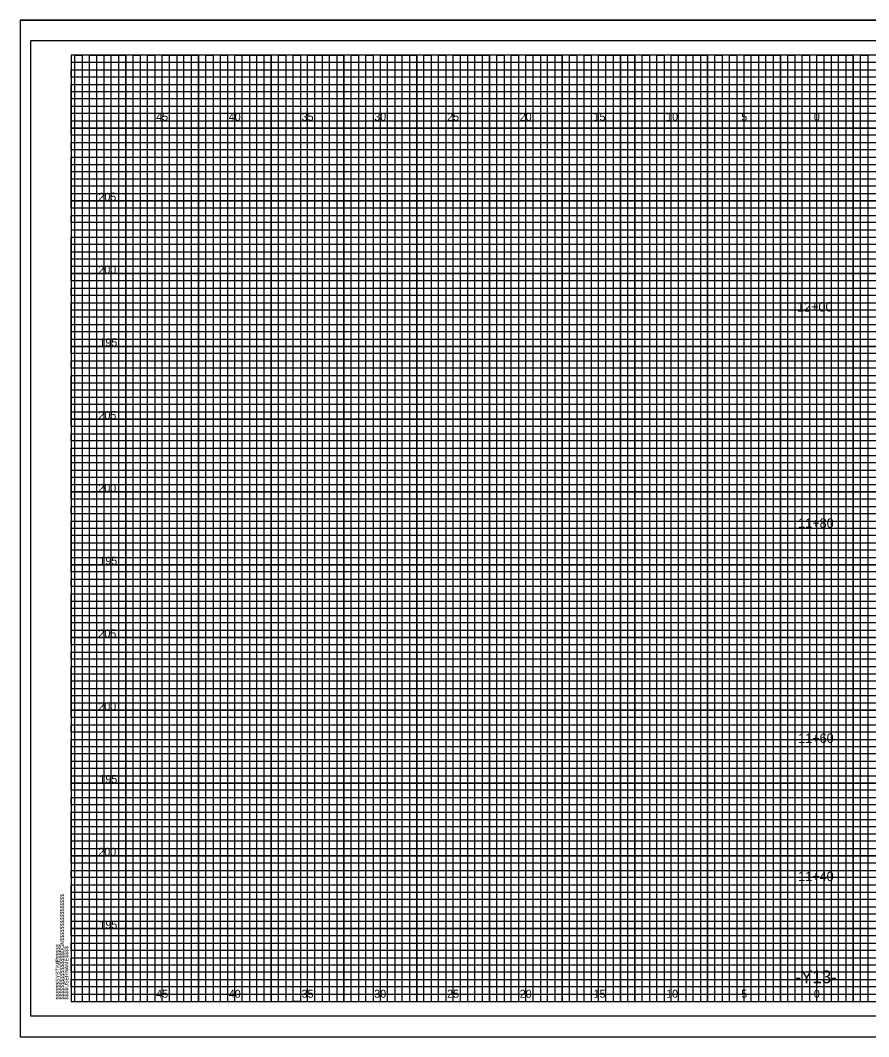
# Model space of a CAD drawing. Extents: x -4 to 103, y -2 to 209.
# Drawn here: x -3.5 to 54.8, y -2.4 to 67.4 of the extents above; entities that cross this region are included whole.
import ezdxf

# ---------------------------------------------------------------- set-up
doc = ezdxf.new("R2010")
doc.units = 0
for name, color, linetype in [('Exist XS Ground Line', 7, 'Continuous'), ('Old_Level_10', 7, 'Continuous'), ('Old_Level_16', 7, 'Continuous'), ('Old_Level_3', 7, 'Continuous'), ('Old_Level_5', 7, 'Continuous'), ('Old_Level_8', 7, 'Continuous'), ('Prop XS Finish Grade Earthwork', 7, 'Continuous'), ('Prop XS Finish Grade Pavement', 7, 'Continuous'), ('Prop XS Pvmt Edge Slope', 7, 'Continuous'), ('Prop XS SE Text', 7, 'Continuous'), ('Prop XS Suitable Common Exc Shape', 7, 'Continuous')]:
    doc.layers.add(name, color=color, linetype=linetype)

msp = doc.modelspace()

# ---------------------------------------------------------------- linework, layer by layer
at = {"layer": 'Exist XS Ground Line'}
msp.add_lwpolyline([(103, 66), (-2.8, 66), (-2.8, -1), (103, -1)], close=True, dxfattribs=at)
at = {"layer": 'Old_Level_10'}
for p, q in [((1.25, 0), (1.25, 65)), ((3.75, 0), (3.75, 65)), ((6.25, 0), (6.25, 65)), ((8.75, 0), (8.75, 65)), ((11.25, 0), (11.25, 65)), ((13.75, 0), (13.75, 65)), ((16.25, 0), (16.25, 65)), ((18.75, 0), (18.75, 65)), ((21.25, 0), (21.25, 65)), ((23.75, 0), (23.75, 65)), ((26.25, 0), (26.25, 65)), ((28.75, 0), (28.75, 65)), ((31.25, 0), (31.25, 65)), ((33.75, 0), (33.75, 65)), ((36.25, 0), (36.25, 65)), ((38.75, 0), (38.75, 65)), ((41.25, 0), (41.25, 65)), ((43.75, 0), (43.75, 65)), ((46.25, 0), (46.25, 65)), ((48.75, 0), (48.75, 65)), ((51.25, 0), (51.25, 65)), ((53.75, 0), (53.75, 65)), ((0, 62.5), (74.25, 62.5)), ((0, 60), (102.5, 60)), ((0, 57.5), (102.5, 57.5)), ((0, 55), (102.5, 55)), ((0, 52.5), (102.5, 52.5)), ((0, 50), (102.5, 50)), ((0, 47.5), (102.5, 47.5)), ((0, 45), (102.5, 45)), ((0, 42.5), (102.5, 42.5)), ((0, 40), (102.5, 40)), ((0, 37.5), (102.5, 37.5)), ((0, 35), (102.5, 35)), ((0, 32.5), (102.5, 32.5)), ((0, 30), (102.5, 30)), ((0, 27.5), (102.5, 27.5)), ((0, 25), (102.5, 25)), ((0, 22.5), (102.5, 22.5)), ((0, 20), (102.5, 20)), ((0, 17.5), (102.5, 17.5)), ((0, 15), (102.5, 15)), ((0, 12.5), (102.5, 12.5)), ((0, 10), (102.5, 10)), ((0, 7.5), (102.5, 7.5)), ((0, 5), (102.5, 5)), ((0, 2.5), (102.5, 2.5))]:
    msp.add_line(p, q, dxfattribs=at)
at = {"layer": 'Old_Level_3'}
for p, q in [((-3.5, 67.4), (103.4, 67.4)), ((-3.5, 67.4), (-3.5, -2.425)), ((-3.5, -2.425), (103.4, -2.425))]:
    msp.add_line(p, q, dxfattribs=at)
at = {"layer": 'Old_Level_5'}
msp.add_lwpolyline([(103.4, 67.4), (-3.5, 67.4), (-3.5, -2.425), (103.4, -2.425)], close=True, dxfattribs=at)
at = {"layer": 'Old_Level_8'}
for points in [[(1.25, 0), (1.25, 65), (3.75, 65), (3.75, 0), (6.25, 0), (6.25, 65), (8.75, 65), (8.75, 0), (11.25, 0), (11.25, 65), (13.75, 65), (13.75, 0), (16.25, 0), (16.25, 65), (18.75, 65), (18.75, 0), (21.25, 0), (21.25, 65), (23.75, 65), (23.75, 0), (26.25, 0), (26.25, 65), (28.75, 65), (28.75, 0), (31.25, 0), (31.25, 65), (33.75, 65), (33.75, 0), (36.25, 0), (36.25, 65), (38.75, 65), (38.75, 0), (41.25, 0), (41.25, 65), (43.75, 65), (43.75, 0), (46.25, 0), (46.25, 65), (48.75, 65), (48.75, 0), (51.25, 0), (51.25, 65), (53.75, 65), (53.75, 0)], [(102.5, 60), (0, 60), (0, 62.5), (74.25, 62.5)], [(102.5, 55), (0, 55), (0, 57.5), (102.5, 57.5)], [(102.5, 50), (0, 50), (0, 52.5), (102.5, 52.5)], [(102.5, 45), (0, 45), (0, 47.5), (102.5, 47.5)], [(102.5, 40), (0, 40), (0, 42.5), (102.5, 42.5)], [(102.5, 35), (0, 35), (0, 37.5), (102.5, 37.5)], [(102.5, 30), (0, 30), (0, 32.5), (102.5, 32.5)], [(102.5, 25), (0, 25), (0, 27.5), (102.5, 27.5)], [(102.5, 20), (0, 20), (0, 22.5), (102.5, 22.5)], [(102.5, 15), (0, 15), (0, 17.5), (102.5, 17.5)], [(102.5, 10), (0, 10), (0, 12.5), (102.5, 12.5)], [(102.5, 5), (0, 5), (0, 7.5), (102.5, 7.5)], [(0, 2.5), (102.5, 2.5)]]:
    msp.add_lwpolyline(points, dxfattribs=at)
at = {"layer": 'Prop XS Finish Grade Earthwork'}
for points in [[(0.25, 0), (0.25, 65), (0.75, 65), (0.75, 0), (1.75, 0), (1.75, 65), (2.25, 65), (2.25, 0), (2.75, 0), (2.75, 65), (3.25, 65), (3.25, 0), (4.25, 0), (4.25, 65), (4.75, 65), (4.75, 0), (5.25, 0), (5.25, 65), (5.75, 65), (5.75, 0), (6.75, 0), (6.75, 65), (7.25, 65), (7.25, 0), (7.75, 0), (7.75, 65), (8.25, 65), (8.25, 0), (9.25, 0), (9.25, 65), (9.75, 65), (9.75, 0), (10.25, 0), (10.25, 65), (10.75, 65), (10.75, 0), (11.75, 0), (11.75, 65), (12.25, 65), (12.25, 0), (12.75, 0), (12.75, 65), (13.25, 65), (13.25, 0), (14.25, 0), (14.25, 65), (14.75, 65), (14.75, 0), (15.75, 0), (15.25, 0), (15.25, 65), (15.75, 65), (15.75, 0), (16.75, 0), (16.75, 65), (17.25, 65), (17.25, 0), (17.75, 0), (17.75, 65), (18.25, 65), (18.25, 0), (19.25, 0), (19.25, 65), (19.75, 65), (19.75, 0), (20.25, 0), (20.25, 65), (20.75, 65), (20.75, 0), (21.75, 0), (21.75, 65), (22.25, 65), (22.25, 0), (22.75, 0), (22.75, 65), (23.25, 65), (23.25, 0), (24.25, 0), (24.25, 65), (24.75, 65), (24.75, 0), (25.25, 0), (25.25, 65), (25.75, 65), (25.75, 0), (26.75, 0), (26.75, 65), (27.25, 65), (27.25, 0), (27.75, 0), (27.75, 65), (28.25, 65), (28.25, 0), (29.25, 0), (29.25, 65), (29.75, 65), (29.75, 0), (30.25, 0), (30.25, 65), (30.75, 65), (30.75, 0)], [(30.75, 0), (31.75, 0), (31.75, 65), (32.25, 65), (32.25, 0), (32.75, 0), (32.75, 65), (33.25, 65), (33.25, 0), (34.25, 0), (34.25, 65), (34.75, 65), (34.75, 0), (35.25, 0), (35.25, 65), (35.75, 65), (35.75, 0), (36.75, 0), (36.75, 65), (37.25, 65), (37.25, 0), (37.75, 0), (37.75, 65), (37.75, 0)], [(38.25, 65), (38.25, 0), (39.25, 0), (39.25, 65), (39.75, 65), (39.75, 0), (40.25, 0), (40.25, 65), (40.75, 65), (40.75, 0), (41.75, 0), (41.75, 65), (42.25, 65), (42.25, 0), (42.75, 0), (42.75, 65), (43.25, 65), (43.25, 0), (43.75, 0), (44.25, 0), (44.25, 65), (44.75, 65), (44.75, 0), (45.25, 0), (45.25, 65), (45.75, 65), (45.75, 0), (46.75, 0), (46.75, 65), (47.25, 65), (47.25, 0), (47.75, 0), (47.75, 65), (48.25, 65), (48.25, 0), (49.25, 0), (49.25, 65), (49.75, 65), (49.75, 0), (50.25, 0), (50.25, 65), (50.75, 65), (50.75, 0), (51.75, 0), (51.75, 65), (52.25, 65), (52.25, 0), (52.75, 0), (52.75, 65), (53.25, 65), (53.25, 0), (54.25, 0), (54.25, 65), (54.75, 65), (54.75, 0), (55.25, 0)], [(0, 62), (0, 63), (74.25, 63), (74.25, 63.5), (0, 63.5), (0, 64), (74.25, 64), (74.25, 64.5), (0, 64.5)], [(102.5, 62), (0, 62)], [(102.5, 61), (0, 61), (0, 61.5), (102.5, 61.5)], [(102.5, 59.5), (0, 59.5), (0, 60.5), (102.5, 60.5)], [(102.5, 58.5), (0, 58.5), (0, 59), (102.5, 59)], [(102.5, 57), (0, 57), (0, 58), (102.5, 58)], [(102.5, 56), (0, 56), (0, 56.5), (102.5, 56.5)], [(102.5, 54.5), (0, 54.5), (0, 55.5), (102.5, 55.5)], [(102.5, 53.5), (0, 53.5), (0, 54), (102.5, 54)], [(0, 53), (102.5, 53)], [(102.5, 52), (0, 52)], [(102.5, 51), (0, 51), (0, 51.5), (102.5, 51.5)], [(102.5, 49.5), (0, 49.5), (0, 50.5), (102.5, 50.5)], [(102.5, 48.5), (0, 48.5), (0, 49), (102.5, 49)], [(102.5, 47), (0, 47), (0, 48), (102.5, 48)], [(102.5, 46), (0, 46), (0, 46.5), (102.5, 46.5)], [(102.5, 44.5), (0, 44.5), (0, 45.5), (102.5, 45.5)], [(102.5, 43.5), (0, 43.5), (0, 44), (102.5, 44)], [(102.5, 42), (0, 42), (0, 43), (102.5, 43)], [(102.5, 41), (0, 41), (0, 41.5), (102.5, 41.5)], [(102.5, 39.5), (0, 39.5), (0, 40.5), (102.5, 40.5)], [(102.5, 38.5), (0, 38.5), (0, 39), (102.5, 39)], [(102.5, 37), (0, 37), (0, 38), (102.5, 38)], [(102.5, 36), (0, 36), (0, 36.5), (102.5, 36.5)], [(102.5, 34.5), (0, 34.5), (0, 35.5), (102.5, 35.5)], [(102.5, 33.5), (0, 33.5), (0, 34), (102.5, 34)], [(102.5, 32), (0, 32), (0, 33), (102.5, 33)], [(102.5, 31), (0, 31), (0, 31.5)], [(0, 31.5), (102.5, 31.5)], [(102.5, 29.5), (0, 29.5), (0, 30.5), (102.5, 30.5)], [(102.5, 28.5), (0, 28.5), (0, 29), (102.5, 29)], [(102.5, 27), (0, 27), (0, 28), (102.5, 28)], [(102.5, 26), (0, 26), (0, 26.5), (102.5, 26.5)], [(102.5, 24.5), (0, 24.5), (0, 25.5), (102.5, 25.5)], [(102.5, 23.5), (0, 23.5), (0, 24), (102.5, 24)], [(102.5, 22), (0, 22), (0, 23), (102.5, 23)], [(102.5, 21), (0, 21), (0, 21.5), (102.5, 21.5)], [(102.5, 19.5), (0, 19.5), (0, 20.5), (102.5, 20.5)], [(102.5, 18.5), (0, 18.5), (0, 19), (102.5, 19)], [(102.5, 17), (0, 17), (0, 18), (102.5, 18)], [(102.5, 16), (0, 16), (0, 16.5), (102.5, 16.5)], [(102.5, 14.5), (0, 14.5), (0, 15.5), (102.5, 15.5)], [(102.5, 13.5), (0, 13.5), (0, 14), (102.5, 14)], [(102.5, 12), (0, 12), (0, 13), (102.5, 13)], [(102.5, 11), (0, 11), (0, 11.5), (102.5, 11.5)], [(102.5, 9.5), (0, 9.5), (0, 10.5), (102.5, 10.5)], [(102.5, 8.5), (0, 8.5), (0, 9), (102.5, 9)], [(102.5, 7), (0, 7), (0, 8), (102.5, 8)], [(102.5, 6), (0, 6), (0, 6.5), (102.5, 6.5)], [(102.5, 4.5), (0, 4.5), (0, 5.5), (102.5, 5.5)], [(102.5, 3.5), (0, 3.5), (0, 4), (102.5, 4)], [(102.5, 2), (0, 2), (0, 3), (102.5, 3)], [(102.5, 1), (0, 1), (0, 1.5), (102.5, 1.5)], [(0, 0.5), (102.5, 0.5)]]:
    msp.add_lwpolyline(points, dxfattribs=at)
at = {"layer": 'Prop XS SE Text'}
msp.add_lwpolyline([(102.5, 65), (0, 65), (0, 0), (102.5, 0)], close=True, dxfattribs=at)

# ---------------------------------------------------------------- texts
at = {"layer": 'Old_Level_16'}
for s, p in [('45', (5.84, 60.5)), ('40', (10.831, 60.5)), ('35', (15.84, 60.5)), ('30', (20.831, 60.5)), ('25', (25.84, 60.5)), ('20', (30.831, 60.5)), ('15', (35.906, 60.5)), ('10', (40.897, 60.5)), ('5', (46.057, 60.5)), ('0', (51.049, 60.5)), ('0', (51.049, 60.5)), ('45', (5.84, 0.25)), ('40', (10.831, 0.25)), ('35', (15.84, 0.25)), ('30', (20.831, 0.25)), ('25', (25.84, 0.25)), ('20', (30.831, 0.25)), ('15', (35.906, 0.25)), ('10', (40.897, 0.25)), ('5', (46.057, 0.25)), ('0', (51.049, 0.25)), ('0', (51.049, 0.25))]:
    msp.add_text(s, height=0.55, dxfattribs=at).set_placement(p)
at = {"layer": 'Old_Level_8'}
msp.add_text('040397', height=0.0025, rotation=90, dxfattribs=at).set_placement((-0.001, 64.986))
at = {"layer": 'Prop XS Finish Grade Pavement'}
for s, p in [('205', (1.872, 55)), ('200', (1.864, 50)), ('195', (1.938, 45)), ('205', (1.872, 40)), ('200', (1.864, 35)), ('195', (1.938, 30)), ('205', (1.872, 25)), ('200', (1.864, 20)), ('195', (1.938, 15)), ('200', (1.864, 10)), ('195', (1.938, 5))]:
    msp.add_text(s, height=0.55, dxfattribs=at).set_placement(p)
at = {"layer": 'Prop XS Pvmt Edge Slope'}
msp.add_text('-Y13-', height=0.875, dxfattribs=at).set_placement((49.773, 1.25))
at = {"layer": 'Prop XS SE Text'}
for s, p in [('$$$$$$$$$$$$$$$$DGN$$$$$$$$$$$$$$$$', (-0.5, 0.125)), ('$$$$$$SYSTIME$$$$$', (-0.797, 0.125)), ('$$$$USERNAME$$$$', (-0.2, 0.125))]:
    msp.add_text(s, height=0.2625, rotation=90, dxfattribs=at).set_placement(p)
at = {"layer": 'Prop XS Suitable Common Exc Shape'}
for s, p in [('12+00', (49.893, 47.392)), ('11+80', (49.971, 32.534)), ('11+60', (49.971, 17.755)), ('11+40', (49.971, 8.264))]:
    msp.add_text(s, height=0.65, dxfattribs=at).set_placement(p)

doc.saveas('drawing.dxf')
